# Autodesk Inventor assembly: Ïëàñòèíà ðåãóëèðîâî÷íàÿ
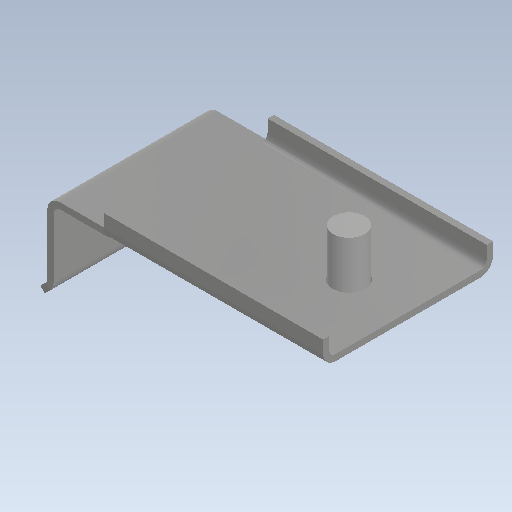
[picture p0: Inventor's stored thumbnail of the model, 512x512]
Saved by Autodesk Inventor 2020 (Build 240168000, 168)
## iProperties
Created: 1900-01
Part Number: Ïëàñòèíà ðåãóëèðîâî÷íàÿ
Document SubType Name: Assembly
Designer: bruno
Author: bruno
Revision Number: ANYUNSPECIFIED
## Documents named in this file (3)
- C:\Users\bruno\Downloads\Ïëàñòèíà ðåãóëèðîâî÷íàÿ.iam
- C:\Users\bruno\Downloads\Ïëàñòèíà ðåãóëèðîâî÷íàÿ.ipt
- C:\Users\bruno\Downloads\Îñü.ipt
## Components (2 placed, 2 different names)
1. 17
2. 18
